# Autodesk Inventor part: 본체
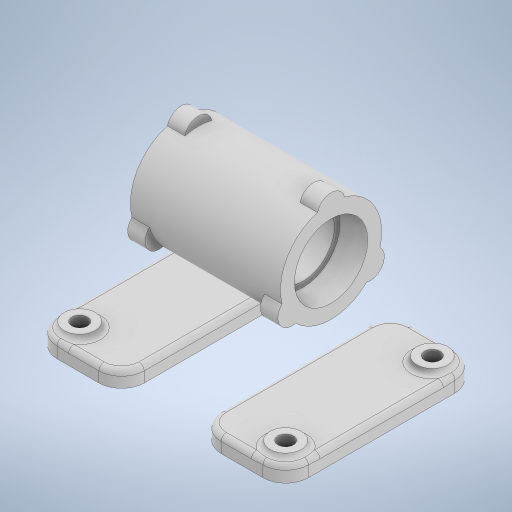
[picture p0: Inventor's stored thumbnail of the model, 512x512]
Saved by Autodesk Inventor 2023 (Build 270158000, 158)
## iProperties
Created: 2026-04
Part Number: 본체
Material: 일반
Document SubType Name: Modeling
Designer: home
Density: 1 g/cm^3
Appearance: 기본값
Author: home
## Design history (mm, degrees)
sketch "스케치1"
  geometry: L1 (-26.777, 0)-(26.777, 0); L2 (0, 0)-(0, 31.451); L3 (-26.777, 72)-(26.777, 72); L4 (-43, 72)-(-43, 101); L5 (-43, 101)-(43, 101); L6 (-43, 93)-(-27, 93); L7 (-27, 93)-(-27, 90); L8 (-27, 90)-(27, 90); L9 (27, 90)-(27, 93); L10 (27, 93)-(43, 93); L11 (43, 101)-(43, 72); 3 further points
  constraints: 22 end point, 5 point on line, 4 perpendicular, 3 horizontal, 3 midpoint, 2 vertical, 2 vertical alignment, 1 coincident, 1 parallel
  dimensions: "d0" = 72 distance from line of point (0, 0) L3; "d1" = 86 distance of L4.end L5.end; "d2" = 42 diameter of L6 L3; "d3" = 58 diameter of L5 L3; "d4" = 36 diameter of L8 L3; "d5" = 16 distance of L6.start L6.end; "d6" = 16 distance of L9.end L10.end
revolve "회전1" sketch "스케치1" stored, may be unused: angle "d7" = 90 deg
sketch "스케치2"
  geometry: L1 (-72.382, 0)-(72.382, 0); L2 (-72.382, -72)-(72.382, -72); L3 (0, 0)-(0, 26); C1 r 34 at (0, 0); C2 r 26 at (0, 0); A1 r 29 centre (0, 0) between (7.761, 27.942) and (-7.761, 27.942) reference; A2 r 8 centre (0, 26) between (7.761, 27.942) and (-7.761, 27.942); A3 r 29 centre (0, 0) between (7.761, 27.942) and (-7.761, 27.942); A4 r 29 centre (0, 0) between (-29, 0) and (29, 0); 4 further points
  constraints: 9 point on circle, 6 end point, 5 centre point, 5 coincident, 2 midpoint, 2 point on line, 1 horizontal, 1 parallel, 1 vertical
  dimensions: "d8" = 72 distance between parallel lines of L1 L2; "d10" = 68 diameter of C1; "d11" = 106 distance of point (0, -72) point (0, 34); "d12" = 52 diameter of C2; "d13" = 26 distance of L3.start L3.end; "d14" = 8 radius of A2
extrude "돌출1" join sketch "스케치2" distance "d15" = 10; taper "d16" = 0 deg
sketch "스케치9"
  geometry: L1 (59, -55)-(35, -55); L2 (22, -42)-(22, 42); L3 (35, 55)-(59, 55); L4 (72, 42)-(72, -42); A1 r 13 centre (59, -42) between (59, -55) and (72, -42); A2 r 13 centre (59, 42) between (72, 42) and (59, 55); A3 r 13 centre (35, 42) between (35, 55) and (22, 42); A4 r 13 centre (35, -42) between (22, -42) and (35, -55); 5 further points
  constraints: 8 end point, 8 point on circle, 8 tangent, 6 point on line, 4 centre point, 3 equal radius, 2 parallel, 1 horizontal, 1 horizontal alignment, 1 midpoint, 1 perpendicular
  dimensions: "d56" = 50 distance of point (72, -55) point (22, -55); "d57" = 110 distance of point (72, 55) point (72, -55); "d58" = 22 distance from line of point (0, 0) L2; "d59" = 13 radius of A1
extrude "돌출4" join sketch "스케치9" distance "d60" = 9; taper "d61" = 0 deg
sketch "스케치10"
  geometry: C1 r 9 at (-59, 42); C2 r 9 at (-59, -42); 1 further point
  constraints: 2 centre point, 1 vertical alignment
  dimensions: "d62" = 18 diameter of C1; "d63" = 18 diameter of C2; "d64" = 42 vertical distance of point (0, 0) C1.centre; "d65" = 42 vertical distance of C2.centre point (0, 0); "d66" = 59 horizontal distance of point (0, 0) C1.centre
extrude "돌출5" join sketch "스케치10" distance "d67" = 3; taper "d68" = 0 deg
fillet "모깎기5" dims "d69" = 3
sketch "스케치11"
  geometry: C1 r 9 at (0, 0) reference; C2 r 9 at (0, -84) reference; 3 further points
  constraints: 2 coincident
hole "구멍3" sketch "스케치11" at (0, 0), (0, -84) diameter "d70" = 9; stored, may be unused: countersink angle "d74" = 90 deg, drill point angle "d76" = 118 deg; dims "d71" = 6, "d72" = 4, "d73" = 2, "d75" = 8
node "솔리드1"
pattern_circular "원형 패턴1" dims angle "d18" = 360 deg
mirror "미러1"
mirror "미러3"
feature "A9D066F2-1C7D-4E18-AEED-F7BC21143FA4" dims "d70" = 9, "d71" = 6, "d72" = 4, "d73" = 2, "d74" = 90 deg, "d75" = 8, "d76" = 118 deg
